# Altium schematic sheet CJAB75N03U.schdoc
size 127 x 101 mm
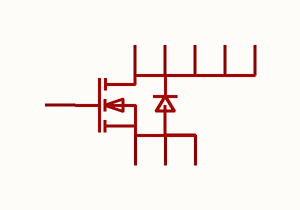
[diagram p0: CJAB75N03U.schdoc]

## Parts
Q?  cjab75n03u  [PDFN-8_L3.2-W3.0-P0.65-LS3.3-BL-1]  (value not drawn)

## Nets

Not connected (* = marked no-connect by the designer): Q? 1(S) 2(S) 3(S) 4(G) 5(D) 6(D) 7(D) 8(D) 9(D)

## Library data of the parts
Q? = cjab75n03u: 数量:1个N沟道;漏源电压(Vdss):30V;连续漏极电流(Id):75A;导通电阻(RDS(on)):4.3mΩ@4.5V;耗散功率(Pd):44W;阈值电压(Vgs(th)):2.2V;; Manufacturer: CJ(江苏长电/长晶); AddInBom: yes; ModelId: 97e5c86264c94fad84e9916fd2a61d33; ModelTransform: 129.921,129.921,0,0,0,0,-0.001,-0.002,0; Number: 1个N沟道; Drain to Source Voltage: 30V; Current - Continuous Drain(Id): 75A; Pd - Power Dissipation: 44W; Gate Threshold Voltage (Vgs(th)): 2.2V; Gate Charge(Qg): 49.7nC@10V; Input Capacitance(Ciss): 3.12nF; Reverse Transfer Capacitance (Crss@Vds): 319pF; Type: N沟道; Output Capacitance(Coss): 387pF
